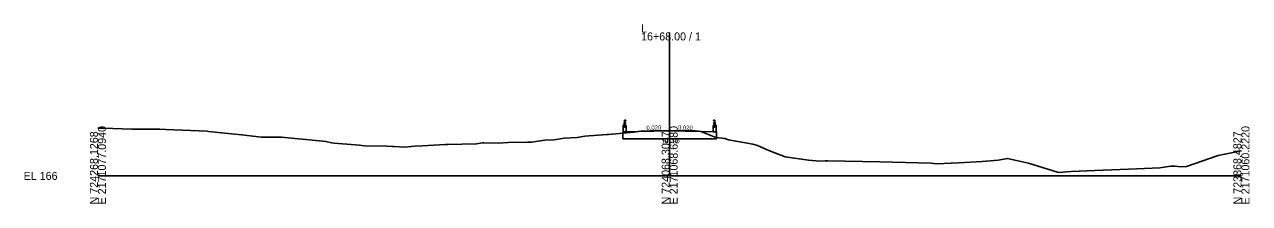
# Model space of a CAD drawing. Extents: x -26 to 2803, y -10 to 9553.
# Drawn here: x -25.7 to 402.8, y 9490.3 to 9553.1 of the extents above; entities that cross this region are included whole.
import ezdxf

# ---------------------------------------------------------------- set-up
doc = ezdxf.new("R2010")
doc.units = 0
for name, color, linetype in [('Exist Cross Section Cell', 7, 'Continuous'), ('Exist XS Center Line Elevation Label', 7, 'Continuous'), ('Exist XS Ground Line', 7, 'Continuous'), ('Prop XS Bridge', 7, 'Continuous'), ('Prop XS Dump Level', 7, 'Continuous'), ('Prop XS SE Text', 7, 'Continuous')]:
    doc.layers.add(name, color=color, linetype=linetype)

msp = doc.modelspace()

# ---------------------------------------------------------------- linework, layer by layer
at = {"layer": 'Exist Cross Section Cell'}
for p, q in [((200, 9500), (200, 9550.27)), ((0, 9500), (200, 9500)), ((200, 9500), (400, 9500))]:
    msp.add_line(p, q, dxfattribs=at)
at = {"layer": 'Exist XS Ground Line'}
msp.add_lwpolyline([(0, 9516.72), (1.79, 9516.76), (11.84, 9516.4), (14.45, 9516.43), (15.04, 9516.4), (21.7, 9516.37), (23.76, 9516.21), (38.2, 9515.64), (38.67, 9515.59), (50.24, 9514.37), (57.26, 9513.58), (59.23, 9513.52), (64.19, 9513.58), (68.93, 9513.13), (72.68, 9512.72), (79.71, 9512.1), (81.76, 9511.61), (82.68, 9511.52), (91.44, 9510.74), (93.21, 9510.59), (101.01, 9510.38), (103.05, 9510.35), (103.57, 9510.35), (107.25, 9510.02), (110.75, 9510.38), (113.56, 9510.57), (121.43, 9511), (122.26, 9511.05), (132.39, 9511.21), (134.52, 9511.55), (135.02, 9511.53), (140.07, 9511.52), (143.53, 9511.69), (150.21, 9511.79), (151.7, 9511.83), (156.31, 9512.5), (159.59, 9512.67), (163.05, 9513.23), (167.61, 9513.5), (170.28, 9513.93), (178.08, 9514.49), (178.59, 9514.51), (187.46, 9515.32), (189.92, 9515.7), (190.7, 9515.72), (193.15, 9515.78), (200.14, 9515.91), (204.77, 9515.83), (208.89, 9515.78), (210.13, 9515.7), (210.94, 9515.6), (216.1, 9513.51), (219.31, 9513.07), (220.61, 9512.67), (229.13, 9511.08), (230.72, 9510.64), (231.81, 9510.13), (234.68, 9508.93), (240.38, 9506.64), (248.54, 9505.47), (252.53, 9505.1), (254.37, 9505.32), (255.34, 9505.33), (273.5, 9504.93), (291.53, 9504.51), (293.34, 9504.28), (301.06, 9504.6), (309.34, 9505.07), (314.97, 9505.52), (318.18, 9506.13), (325.58, 9504.5), (336.07, 9501.18), (340.48, 9501.56), (348.73, 9501.87), (363.43, 9502.44), (371.48, 9502.82), (375.26, 9503.38), (376.74, 9503.37), (377.73, 9503.27), (379.2, 9503.23), (380.83, 9503.31), (391.86, 9507.15), (400, 9508.8)], dxfattribs=at)
at = {"layer": 'Prop XS Bridge'}
for p, q in [((183.69, 9517.69), (183.73, 9517.73)), ((184.7, 9517.73), (183.73, 9517.73)), ((184.19, 9519.52), (184.07, 9517.81)), ((184.07, 9517.83), (184.07, 9517.86)), ((184.07, 9517.77), (184.07, 9517.81)), ((184.18, 9517.84), (184.14, 9517.84)), ((184.14, 9517.84), (184.14, 9517.81)), ((184.14, 9517.69), (184.14, 9517.77)), ((184.18, 9517.81), (184.18, 9517.84)), ((184.18, 9517.69), (184.18, 9517.77)), ((184.19, 9519.52), (184.3, 9519.56)), ((184.19, 9517.77), (184.19, 9519.52)), ((184.19, 9518.7), (184.19, 9518.7)), ((184.37, 9519.56), (184.3, 9519.56)), ((184.3, 9517.77), (184.3, 9519.56)), ((184.37, 9517.77), (184.37, 9519.56)), ((184.43, 9519.53), (184.43, 9519.43)), ((184.43, 9519.33), (184.43, 9519.43)), ((184.43, 9518.59), (184.43, 9518.49)), ((184.43, 9518.4), (184.43, 9518.49)), ((184.51, 9517.85), (184.47, 9517.85)), ((184.47, 9517.85), (184.47, 9517.82)), ((184.47, 9517.7), (184.47, 9517.78)), ((184.51, 9517.82), (184.51, 9517.85)), ((184.51, 9517.7), (184.51, 9517.78)), ((184.7, 9517.73), (184.75, 9517.69)), ((215.25, 9517.69), (215.3, 9517.73)), ((215.3, 9517.73), (216.27, 9517.73)), ((215.49, 9517.82), (215.49, 9517.85)), ((215.49, 9517.85), (215.53, 9517.85)), ((215.49, 9517.7), (215.49, 9517.78)), ((215.53, 9517.85), (215.53, 9517.82)), ((215.53, 9517.7), (215.53, 9517.78)), ((215.57, 9519.53), (215.57, 9519.43)), ((215.57, 9519.33), (215.57, 9519.43)), ((215.57, 9518.59), (215.57, 9518.49)), ((215.57, 9518.4), (215.57, 9518.49)), ((215.63, 9519.56), (215.7, 9519.56)), ((215.63, 9517.77), (215.63, 9519.56)), ((215.81, 9519.52), (215.7, 9519.56)), ((215.7, 9517.77), (215.7, 9519.56)), ((215.81, 9517.77), (215.81, 9519.52)), ((215.81, 9519.52), (215.93, 9517.81)), ((215.81, 9518.7), (215.81, 9518.7)), ((215.82, 9517.81), (215.82, 9517.84)), ((215.82, 9517.84), (215.86, 9517.84)), ((215.82, 9517.69), (215.82, 9517.77)), ((215.86, 9517.84), (215.86, 9517.81)), ((215.86, 9517.69), (215.86, 9517.77)), ((215.93, 9517.83), (215.93, 9517.86)), ((215.93, 9517.77), (215.93, 9517.81)), ((216.27, 9517.73), (216.31, 9517.69)), ((183.57, 9515.41), (183.62, 9515.46)), ((183.57, 9515.41), (183.57, 9512.96)), ((183.7, 9515.46), (183.62, 9515.46)), ((183.69, 9517.69), (183.69, 9515.46)), ((184.75, 9515.46), (183.7, 9515.46)), ((184.2, 9517.7), (184.11, 9517.7)), ((184.2, 9517.69), (184.11, 9517.69)), ((184.15, 9517.66), (184.11, 9517.66)), ((184.15, 9517.65), (184.11, 9517.65)), ((184.15, 9517.62), (184.11, 9517.62)), ((184.15, 9517.6), (184.11, 9517.6)), ((184.15, 9517.57), (184.11, 9517.57)), ((184.15, 9517.56), (184.11, 9517.56)), ((184.15, 9517.53), (184.11, 9517.53)), ((184.15, 9517.52), (184.11, 9517.52)), ((184.15, 9517.68), (184.13, 9517.68)), ((184.15, 9517.67), (184.13, 9517.67)), ((184.15, 9517.64), (184.13, 9517.64)), ((184.15, 9517.63), (184.13, 9517.63)), ((184.15, 9517.59), (184.13, 9517.59)), ((184.15, 9517.58), (184.13, 9517.58)), ((184.15, 9517.55), (184.13, 9517.55)), ((184.15, 9517.54), (184.13, 9517.54)), ((184.16, 9517.68), (184.15, 9517.68)), ((184.15, 9517.68), (184.15, 9517.17)), ((184.18, 9517.68), (184.16, 9517.68)), ((184.16, 9517.68), (184.16, 9517.17)), ((184.18, 9517.67), (184.16, 9517.67)), ((184.2, 9517.66), (184.16, 9517.66)), ((184.2, 9517.65), (184.16, 9517.65)), ((184.18, 9517.64), (184.16, 9517.64)), ((184.18, 9517.63), (184.16, 9517.63)), ((184.2, 9517.62), (184.16, 9517.62)), ((184.2, 9517.6), (184.16, 9517.6)), ((184.18, 9517.59), (184.16, 9517.59)), ((184.18, 9517.58), (184.16, 9517.58)), ((184.2, 9517.57), (184.16, 9517.57)), ((184.2, 9517.56), (184.16, 9517.56)), ((184.18, 9517.55), (184.16, 9517.55)), ((184.18, 9517.54), (184.16, 9517.54)), ((184.2, 9517.53), (184.16, 9517.53)), ((184.2, 9517.52), (184.16, 9517.52)), ((184.43, 9517.12), (184.21, 9517.12)), ((184.43, 9517.11), (184.21, 9517.11)), ((184.53, 9517.7), (184.44, 9517.7)), ((184.53, 9517.69), (184.44, 9517.69)), ((184.48, 9517.66), (184.44, 9517.66)), ((184.48, 9517.65), (184.44, 9517.65)), ((184.48, 9517.62), (184.44, 9517.62)), ((184.48, 9517.6), (184.44, 9517.6)), ((184.48, 9517.57), (184.44, 9517.57)), ((184.48, 9517.56), (184.44, 9517.56)), ((184.48, 9517.53), (184.44, 9517.53)), ((184.48, 9517.52), (184.44, 9517.52)), ((184.48, 9517.68), (184.46, 9517.68)), ((184.48, 9517.67), (184.46, 9517.67)), ((184.48, 9517.64), (184.46, 9517.64)), ((184.48, 9517.63), (184.46, 9517.63)), ((184.48, 9517.59), (184.46, 9517.59)), ((184.48, 9517.58), (184.46, 9517.58)), ((184.48, 9517.55), (184.46, 9517.55)), ((184.48, 9517.54), (184.46, 9517.54)), ((184.49, 9517.68), (184.48, 9517.68)), ((184.48, 9517.68), (184.48, 9517.17)), ((184.51, 9517.68), (184.49, 9517.68)), ((184.49, 9517.68), (184.49, 9517.17)), ((184.51, 9517.67), (184.49, 9517.67)), ((184.53, 9517.66), (184.49, 9517.66)), ((184.53, 9517.65), (184.49, 9517.65)), ((184.51, 9517.64), (184.49, 9517.64)), ((184.51, 9517.63), (184.49, 9517.63)), ((184.53, 9517.62), (184.49, 9517.62)), ((184.53, 9517.6), (184.49, 9517.6)), ((184.51, 9517.59), (184.49, 9517.59)), ((184.51, 9517.58), (184.49, 9517.58)), ((184.53, 9517.57), (184.49, 9517.57)), ((184.53, 9517.56), (184.49, 9517.56)), ((184.51, 9517.55), (184.49, 9517.55)), ((184.51, 9517.54), (184.49, 9517.54)), ((184.53, 9517.53), (184.49, 9517.53)), ((184.53, 9517.52), (184.49, 9517.52)), ((184.75, 9517.69), (184.75, 9515.46)), ((189, 9515.54), (184.75, 9515.46)), ((189, 9515.54), (200, 9515.76)), ((200, 9515.76), (211, 9515.54)), ((211, 9515.54), (215.25, 9515.46)), ((215.25, 9517.69), (215.25, 9515.46)), ((215.25, 9515.46), (216.3, 9515.46)), ((215.47, 9517.7), (215.56, 9517.7)), ((215.47, 9517.69), (215.56, 9517.69)), ((215.47, 9517.66), (215.51, 9517.66)), ((215.47, 9517.65), (215.51, 9517.65)), ((215.47, 9517.62), (215.51, 9517.62)), ((215.47, 9517.6), (215.51, 9517.6)), ((215.47, 9517.57), (215.51, 9517.57)), ((215.47, 9517.56), (215.51, 9517.56)), ((215.47, 9517.53), (215.51, 9517.53)), ((215.47, 9517.52), (215.51, 9517.52)), ((215.49, 9517.68), (215.51, 9517.68)), ((215.49, 9517.67), (215.51, 9517.67)), ((215.49, 9517.64), (215.51, 9517.64)), ((215.49, 9517.63), (215.51, 9517.63)), ((215.49, 9517.59), (215.51, 9517.59)), ((215.49, 9517.58), (215.51, 9517.58)), ((215.49, 9517.55), (215.51, 9517.55)), ((215.49, 9517.54), (215.51, 9517.54)), ((215.51, 9517.68), (215.52, 9517.68)), ((215.51, 9517.68), (215.51, 9517.17)), ((215.52, 9517.68), (215.54, 9517.68)), ((215.52, 9517.68), (215.52, 9517.17)), ((215.52, 9517.67), (215.54, 9517.67)), ((215.52, 9517.66), (215.56, 9517.66)), ((215.52, 9517.65), (215.56, 9517.65)), ((215.52, 9517.64), (215.54, 9517.64)), ((215.52, 9517.63), (215.54, 9517.63)), ((215.52, 9517.62), (215.56, 9517.62)), ((215.52, 9517.6), (215.56, 9517.6)), ((215.52, 9517.59), (215.54, 9517.59)), ((215.52, 9517.58), (215.54, 9517.58)), ((215.52, 9517.57), (215.56, 9517.57)), ((215.52, 9517.56), (215.56, 9517.56)), ((215.52, 9517.55), (215.54, 9517.55)), ((215.52, 9517.54), (215.54, 9517.54)), ((215.52, 9517.53), (215.56, 9517.53)), ((215.52, 9517.52), (215.56, 9517.52)), ((215.57, 9517.12), (215.79, 9517.12)), ((215.57, 9517.11), (215.79, 9517.11)), ((215.8, 9517.7), (215.89, 9517.7)), ((215.8, 9517.69), (215.89, 9517.69)), ((215.8, 9517.66), (215.84, 9517.66)), ((215.8, 9517.65), (215.84, 9517.65)), ((215.8, 9517.62), (215.84, 9517.62)), ((215.8, 9517.6), (215.84, 9517.6)), ((215.8, 9517.57), (215.84, 9517.57)), ((215.8, 9517.56), (215.84, 9517.56)), ((215.8, 9517.53), (215.84, 9517.53)), ((215.8, 9517.52), (215.84, 9517.52)), ((215.82, 9517.68), (215.84, 9517.68)), ((215.82, 9517.67), (215.84, 9517.67)), ((215.82, 9517.64), (215.84, 9517.64)), ((215.82, 9517.63), (215.84, 9517.63)), ((215.82, 9517.59), (215.84, 9517.59)), ((215.82, 9517.58), (215.84, 9517.58)), ((215.82, 9517.55), (215.84, 9517.55)), ((215.82, 9517.54), (215.84, 9517.54)), ((215.84, 9517.68), (215.85, 9517.68)), ((215.84, 9517.68), (215.84, 9517.17)), ((215.85, 9517.68), (215.87, 9517.68)), ((215.85, 9517.68), (215.85, 9517.17)), ((215.85, 9517.67), (215.87, 9517.67)), ((215.85, 9517.66), (215.89, 9517.66)), ((215.85, 9517.65), (215.89, 9517.65)), ((215.85, 9517.64), (215.87, 9517.64)), ((215.85, 9517.63), (215.87, 9517.63)), ((215.85, 9517.62), (215.89, 9517.62)), ((215.85, 9517.6), (215.89, 9517.6)), ((215.85, 9517.59), (215.87, 9517.59)), ((215.85, 9517.58), (215.87, 9517.58)), ((215.85, 9517.57), (215.89, 9517.57)), ((215.85, 9517.56), (215.89, 9517.56)), ((215.85, 9517.55), (215.87, 9517.55)), ((215.85, 9517.54), (215.87, 9517.54)), ((215.85, 9517.53), (215.89, 9517.53)), ((215.85, 9517.52), (215.89, 9517.52)), ((216.3, 9515.46), (216.38, 9515.46)), ((216.31, 9517.69), (216.31, 9515.46)), ((216.43, 9515.41), (216.38, 9515.46)), ((216.43, 9515.41), (216.43, 9512.96)), ((216.43, 9512.96), (183.57, 9512.96))]:
    msp.add_line(p, q, dxfattribs=at)
for points in [[(184.55, 9517.73), (184.55, 9517.78), (184.39, 9517.78), (184.39, 9518.15), (184.37, 9518.15), (184.37, 9517.77), (184.07, 9517.77), (184.07, 9517.8), (184.07, 9517.8), (184.07, 9517.73), (184.21, 9517.73), (184.21, 9517.76), (184.35, 9517.76), (184.35, 9517.73), (184.55, 9517.73)], [(184.2, 9517.77), (184.2, 9517.78), (184.16, 9517.78), (184.12, 9517.78), (184.12, 9517.77)], [(184.19, 9517.78), (184.19, 9517.8), (184.18, 9517.81), (184.13, 9517.81), (184.13, 9517.8), (184.13, 9517.78), (184.19, 9517.78), (184.17, 9517.78), (184.17, 9517.8), (184.17, 9517.81), (184.17, 9517.8), (184.16, 9517.81), (184.15, 9517.81), (184.15, 9517.8), (184.15, 9517.78), (184.15, 9517.8), (184.14, 9517.81)], [(184.37, 9519.31), (184.37, 9519.35), (184.39, 9519.35), (184.39, 9519.35), (184.39, 9519.35), (184.39, 9519.33), (184.42, 9519.33), (184.42, 9519.36), (184.42, 9519.43), (184.42, 9519.51), (184.42, 9519.54), (184.39, 9519.54), (184.39, 9519.52), (184.39, 9519.52), (184.39, 9519.51), (184.37, 9519.51), (184.37, 9519.56)], [(184.37, 9518.37), (184.37, 9518.42), (184.39, 9518.42), (184.39, 9518.41), (184.39, 9518.41), (184.39, 9518.39), (184.42, 9518.39), (184.42, 9518.42), (184.42, 9518.49), (184.42, 9518.57), (184.42, 9518.6), (184.39, 9518.6), (184.39, 9518.58), (184.39, 9518.58), (184.39, 9518.57), (184.37, 9518.57), (184.37, 9518.62)], [(184.53, 9517.78), (184.53, 9517.79), (184.49, 9517.79), (184.45, 9517.79), (184.45, 9517.78)], [(184.52, 9517.79), (184.52, 9517.81), (184.51, 9517.82), (184.46, 9517.82), (184.46, 9517.81), (184.46, 9517.79), (184.52, 9517.79), (184.5, 9517.79), (184.5, 9517.81), (184.5, 9517.82), (184.5, 9517.81), (184.49, 9517.82), (184.48, 9517.82), (184.48, 9517.81), (184.48, 9517.79), (184.48, 9517.81), (184.47, 9517.82)], [(215.45, 9517.73), (215.45, 9517.78), (215.61, 9517.78), (215.61, 9518.15), (215.63, 9518.15), (215.63, 9517.77), (215.93, 9517.77), (215.93, 9517.8), (215.93, 9517.8), (215.93, 9517.73), (215.79, 9517.73), (215.79, 9517.76), (215.65, 9517.76), (215.65, 9517.73), (215.45, 9517.73)], [(215.47, 9517.78), (215.47, 9517.79), (215.51, 9517.79), (215.55, 9517.79), (215.55, 9517.78)], [(215.48, 9517.79), (215.48, 9517.81), (215.49, 9517.82), (215.54, 9517.82), (215.54, 9517.81), (215.54, 9517.79), (215.48, 9517.79), (215.5, 9517.79), (215.5, 9517.81), (215.5, 9517.82), (215.5, 9517.81), (215.51, 9517.82), (215.52, 9517.82), (215.52, 9517.81), (215.52, 9517.79), (215.52, 9517.81), (215.53, 9517.82)], [(215.63, 9519.31), (215.63, 9519.35), (215.61, 9519.35), (215.61, 9519.35), (215.61, 9519.35), (215.61, 9519.33), (215.58, 9519.33), (215.58, 9519.36), (215.58, 9519.43), (215.58, 9519.51), (215.58, 9519.54), (215.61, 9519.54), (215.61, 9519.52), (215.61, 9519.52), (215.61, 9519.51), (215.63, 9519.51), (215.63, 9519.56)], [(215.63, 9518.37), (215.63, 9518.42), (215.61, 9518.42), (215.61, 9518.41), (215.61, 9518.41), (215.61, 9518.39), (215.58, 9518.39), (215.58, 9518.42), (215.58, 9518.49), (215.58, 9518.57), (215.58, 9518.6), (215.61, 9518.6), (215.61, 9518.58), (215.61, 9518.58), (215.61, 9518.57), (215.63, 9518.57), (215.63, 9518.62)], [(215.8, 9517.77), (215.8, 9517.78), (215.84, 9517.78), (215.88, 9517.78), (215.88, 9517.77)], [(215.81, 9517.78), (215.81, 9517.8), (215.82, 9517.81), (215.87, 9517.81), (215.87, 9517.8), (215.87, 9517.78), (215.81, 9517.78), (215.83, 9517.78), (215.83, 9517.8), (215.83, 9517.81), (215.83, 9517.8), (215.84, 9517.81), (215.85, 9517.81), (215.85, 9517.8), (215.85, 9517.78), (215.85, 9517.8), (215.86, 9517.81)], [(184.11, 9517.7), (184.11, 9517.69), (184.13, 9517.68), (184.13, 9517.67), (184.11, 9517.66), (184.11, 9517.65), (184.13, 9517.64), (184.13, 9517.63), (184.11, 9517.62), (184.11, 9517.6), (184.13, 9517.59), (184.13, 9517.58), (184.11, 9517.57), (184.11, 9517.56), (184.13, 9517.55), (184.13, 9517.54), (184.11, 9517.53), (184.11, 9517.52)], [(184.2, 9517.7), (184.2, 9517.69), (184.18, 9517.68), (184.18, 9517.67), (184.2, 9517.66), (184.2, 9517.65), (184.18, 9517.64), (184.18, 9517.63), (184.2, 9517.62), (184.2, 9517.6), (184.18, 9517.59), (184.18, 9517.58), (184.2, 9517.57), (184.2, 9517.56), (184.18, 9517.55), (184.18, 9517.54), (184.2, 9517.53), (184.2, 9517.52)], [(184.44, 9517.7), (184.44, 9517.69), (184.46, 9517.68), (184.46, 9517.67), (184.44, 9517.66), (184.44, 9517.65), (184.46, 9517.64), (184.46, 9517.63), (184.44, 9517.62), (184.44, 9517.6), (184.46, 9517.59), (184.46, 9517.58), (184.44, 9517.57), (184.44, 9517.56), (184.46, 9517.55), (184.46, 9517.54), (184.44, 9517.53), (184.44, 9517.52)], [(184.53, 9517.7), (184.53, 9517.69), (184.51, 9517.68), (184.51, 9517.67), (184.53, 9517.66), (184.53, 9517.65), (184.51, 9517.64), (184.51, 9517.63), (184.53, 9517.62), (184.53, 9517.6), (184.51, 9517.59), (184.51, 9517.58), (184.53, 9517.57), (184.53, 9517.56), (184.51, 9517.55), (184.51, 9517.54), (184.53, 9517.53), (184.53, 9517.52)], [(215.47, 9517.7), (215.47, 9517.69), (215.49, 9517.68), (215.49, 9517.67), (215.47, 9517.66), (215.47, 9517.65), (215.49, 9517.64), (215.49, 9517.63), (215.47, 9517.62), (215.47, 9517.6), (215.49, 9517.59), (215.49, 9517.58), (215.47, 9517.57), (215.47, 9517.56), (215.49, 9517.55), (215.49, 9517.54), (215.47, 9517.53), (215.47, 9517.52)], [(215.56, 9517.7), (215.56, 9517.69), (215.54, 9517.68), (215.54, 9517.67), (215.56, 9517.66), (215.56, 9517.65), (215.54, 9517.64), (215.54, 9517.63), (215.56, 9517.62), (215.56, 9517.6), (215.54, 9517.59), (215.54, 9517.58), (215.56, 9517.57), (215.56, 9517.56), (215.54, 9517.55), (215.54, 9517.54), (215.56, 9517.53), (215.56, 9517.52)], [(215.8, 9517.7), (215.8, 9517.69), (215.82, 9517.68), (215.82, 9517.67), (215.8, 9517.66), (215.8, 9517.65), (215.82, 9517.64), (215.82, 9517.63), (215.8, 9517.62), (215.8, 9517.6), (215.82, 9517.59), (215.82, 9517.58), (215.8, 9517.57), (215.8, 9517.56), (215.82, 9517.55), (215.82, 9517.54), (215.8, 9517.53), (215.8, 9517.52)], [(215.89, 9517.7), (215.89, 9517.69), (215.87, 9517.68), (215.87, 9517.67), (215.89, 9517.66), (215.89, 9517.65), (215.87, 9517.64), (215.87, 9517.63), (215.89, 9517.62), (215.89, 9517.6), (215.87, 9517.59), (215.87, 9517.58), (215.89, 9517.57), (215.89, 9517.56), (215.87, 9517.55), (215.87, 9517.54), (215.89, 9517.53), (215.89, 9517.52)]]:
    msp.add_lwpolyline(points, dxfattribs=at)
for centre in [(184.12, 9517.55), (184.53, 9517.55), (215.47, 9517.55), (215.88, 9517.55)]:
    msp.add_circle(centre, 0.00793, dxfattribs=at)
for centre, radius, start, end in [((184.44, 9519.53), 0.00744, 90, 180), ((184.44, 9519.33), 0.00744, 180, 270), ((184.44, 9518.59), 0.00744, 90, 180), ((184.44, 9518.4), 0.00744, 180, 270), ((215.56, 9519.53), 0.00744, 0, 90), ((215.56, 9519.33), 0.00744, 270, 360), ((215.56, 9518.59), 0.00744, 0, 90), ((215.56, 9518.4), 0.00744, 270, 360), ((184.21, 9517.17), 0.0665, 180, 270), ((184.21, 9517.17), 0.0507, 180, 270), ((184.43, 9517.17), 0.0507, 270, 0), ((184.43, 9517.17), 0.0665, 270, 0), ((215.57, 9517.17), 0.0665, 180, 270), ((215.57, 9517.17), 0.0507, 180, 270), ((215.79, 9517.17), 0.0507, 270, 0), ((215.79, 9517.17), 0.0665, 270, 0)]:
    msp.add_arc(centre, radius, start, end, dxfattribs=at)
for centre, major_axis, ratio, start_param, end_param in [((184.37, 9519.43), (0.318, 0), 0.39036, 6.282787, 7.853967), ((184.37, 9519.43), (0.318, 0), 0.39036, 4.712404, 6.282787), ((184.37, 9518.49), (0.318, 0), 0.39036, 6.282787, 7.853967), ((184.37, 9518.49), (0.318, 0), 0.39036, 4.712404, 6.282787), ((184.44, 9519.43), (0.211, 0), 0.495501, 6.282718, 7.853881), ((184.44, 9519.43), (0.211, 0), 0.495501, 4.712489, 6.282718), ((184.44, 9518.49), (0.211, 0), 0.495501, 6.282718, 7.853881), ((184.44, 9518.49), (0.211, 0), 0.495501, 4.712489, 6.282718), ((215.63, 9519.43), (-0.318, 0), 0.39036, 4.712404, 6.283584), ((215.63, 9519.43), (-0.318, 0), 0.39036, 0.000398, 1.570782), ((215.63, 9518.49), (-0.318, 0), 0.39036, 4.712404, 6.283584), ((215.63, 9518.49), (-0.318, 0), 0.39036, 0.000398, 1.570782), ((215.56, 9519.43), (-0.211, 0), 0.495501, 4.712489, 6.283652), ((215.56, 9519.43), (-0.211, 0), 0.495501, 0.000467, 1.570696), ((215.56, 9518.49), (-0.211, 0), 0.495501, 4.712489, 6.283652), ((215.56, 9518.49), (-0.211, 0), 0.495501, 0.000467, 1.570696)]:
    msp.add_ellipse(centre, major_axis=major_axis, ratio=ratio, start_param=start_param, end_param=end_param, dxfattribs=at)
at = {"layer": 'Prop XS Dump Level'}
for p, q in [((189, 9515.54), (200, 9515.76)), ((200, 9515.76), (211, 9515.54))]:
    msp.add_line(p, q, dxfattribs=at)

# ---------------------------------------------------------------- texts
at = {"layer": 'Exist Cross Section Cell'}
for s, p in [('L', (190, 9550.27)), ('16+68.00 / 1', (190, 9547.47)), ('EL 166', (-26, 9498.6))]:
    msp.add_text(s, height=2.8, dxfattribs=at).set_placement(p)
for s, p in [('N 724268.1268', (0, 9490)), ('E 2171077.0940', (2.8, 9490)), ('N 724068.3047', (200, 9490)), ('E 2171068.6580', (202.8, 9490)), ('N 723868.4827', (400, 9490)), ('E 2171060.2220', (402.8, 9490))]:
    msp.add_text(s, height=2.8, rotation=90, dxfattribs=at).set_placement(p)
at = {"layer": 'Exist XS Center Line Elevation Label'}
msp.add_text('181.90', height=1.5, dxfattribs=at).set_placement((197.14, 9511.4))
at = {"layer": 'Prop XS SE Text'}
for rotation, p in [(1.1458, (191.88, 9516.1)), (358.8542, (202.88, 9516.21))]:
    msp.add_text('0.020', height=1.5, rotation=rotation, dxfattribs=at).set_placement(p)

doc.saveas('drawing.dxf')
